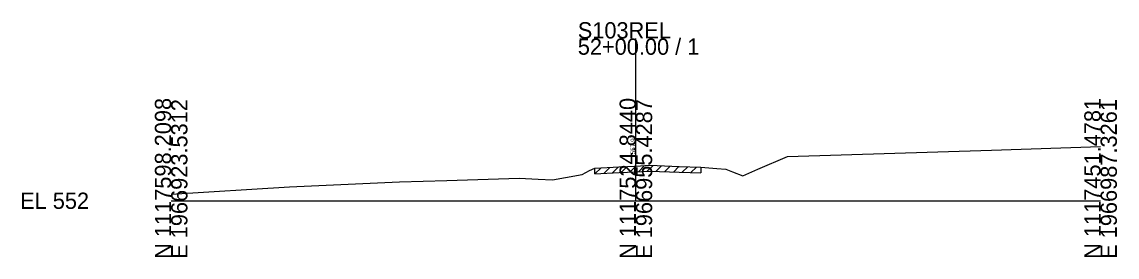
# Model space of a CAD drawing. Extents: x -26 to 163, y -10 to 24518.
# Drawn here: x -25.7 to 162.8, y 2490.3 to 2530.8 of the extents above; entities that cross this region are included whole.
import ezdxf

# ---------------------------------------------------------------- set-up
doc = ezdxf.new("R2010")
doc.units = 0
for name, color, linetype in [('RD_GPK_XS_Cell', 7, 'Continuous'), ('RD_XS_ExGround', 7, 'Continuous'), ('RD_XS_ExPaveRet', 7, 'Continuous'), ('RD_XS_TX_Elev_EX', 7, 'Continuous')]:
    doc.layers.add(name, color=color, linetype=linetype)

msp = doc.modelspace()

# ---------------------------------------------------------------- linework, layer by layer
at = {"layer": 'RD_GPK_XS_Cell'}
for p, q in [((80, 2500), (80, 2527.91)), ((0, 2500), (80, 2500)), ((80, 2500), (160, 2500))]:
    msp.add_line(p, q, dxfattribs=at)
at = {"layer": 'RD_XS_ExGround'}
msp.add_lwpolyline([(0, 2501.1), (20.39, 2502.4), (39.33, 2503.26), (47.45, 2503.5), (59.89, 2503.86), (63.18, 2503.71), (65.63, 2503.62), (67.91, 2504.02), (70.75, 2504.51), (72, 2505.18), (72.96, 2505.61), (77.15, 2505.83), (80, 2505.97), (82.41, 2506.09), (87.48, 2505.9), (91.2, 2505.77), (93.93, 2505.55), (95.48, 2505.43), (96.62, 2504.99), (98.39, 2504.27), (101.02, 2505.42), (106.11, 2507.61), (141.2, 2508.72), (160, 2509.3)], dxfattribs=at)
at = {"layer": 'RD_XS_ExPaveRet'}
for p, q in [((72.96, 2504.61), (74.01, 2505.66)), ((72.96, 2504.61), (72.96, 2505.61)), ((74.46, 2504.69), (75.51, 2505.74)), ((75.96, 2504.77), (77.01, 2505.82)), ((77.46, 2504.85), (78.51, 2505.9)), ((78.96, 2504.92), (80.01, 2505.97)), ((80.46, 2504.99), (81.51, 2506.05)), ((81.96, 2505.07), (82.96, 2506.07)), ((83.46, 2505.05), (84.42, 2506.02)), ((84.96, 2505), (85.92, 2505.96)), ((86.46, 2504.94), (87.42, 2505.91)), ((87.96, 2504.89), (88.92, 2505.85)), ((89.46, 2504.83), (90.42, 2505.8)), ((91.2, 2505.77), (91.2, 2504.77)), ((72.96, 2504.61), (77.15, 2504.83)), ((77.15, 2504.83), (80, 2504.97)), ((80, 2504.97), (82.41, 2505.09)), ((82.41, 2505.09), (87.48, 2504.9)), ((87.48, 2504.9), (91.2, 2504.77))]:
    msp.add_line(p, q, dxfattribs=at)

# ---------------------------------------------------------------- texts
at = {"layer": 'RD_GPK_XS_Cell'}
for s, p in [('S103REL', (70, 2527.91)), ('52+00.00 / 1', (70, 2525.11)), ('EL 552', (-26, 2498.6))]:
    msp.add_text(s, height=2.8, dxfattribs=at).set_placement(p)
for s, p in [('N 1117598.2098', (0, 2490)), ('E 1966923.5312', (2.8, 2490)), ('N 1117524.8440', (80, 2490)), ('E 1966955.4287', (82.8, 2490)), ('N 1117451.4781', (160, 2490)), ('E 1966987.3261', (162.8, 2490))]:
    msp.add_text(s, height=2.8, rotation=90, dxfattribs=at).set_placement(p)
at = {"layer": 'RD_XS_TX_Elev_EX'}
msp.add_text('557.97', height=0.8, rotation=90, dxfattribs=at).set_placement((79.9, 2507.97))

doc.saveas('drawing.dxf')
